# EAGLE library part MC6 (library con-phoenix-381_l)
Mini-Combicon 3.81mm horizontal 6-polig (ohne Gegenstecker)
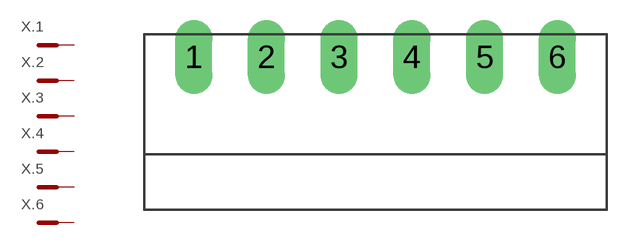
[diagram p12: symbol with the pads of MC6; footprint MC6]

Designator prefix X; gates .1=MCST .2=MCST .3=MCST .4=MCST .5=MCST .6=MCST

## MC6  [MC6]
1  .1:SK  pas
2  .2:SK  pas
3  .3:SK  pas
4  .4:SK  pas
5  .5:SK  pas
6  .6:SK  pas

## Footprint MC6 (pad centres in mm)
Mini-Combicon 3.81mm horizontal 6-polig (ohne Gegenstecker)
drill 1.3 long: 1 -9.525,0; 2 -5.715,0; 3 -1.905,0; 4 1.905,0; 5 5.715,0; 6 9.525,0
